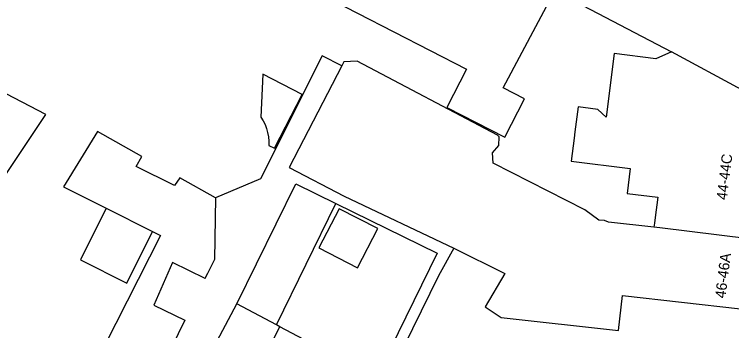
# Model space of a CAD drawing. Extents: x 160356 to 161355, y 381727 to 382845.
# Drawn here: x 160817.9 to 160886, y 382494.8 to 382524.8 of the extents above; entities that cross this region are included whole.
import ezdxf

# ---------------------------------------------------------------- set-up
doc = ezdxf.new("R2010")
doc.units = 0
for name, color, linetype in [('IMGEO_Pand', 7, 'Continuous'), ('IMGEO_Pand_nummerreeks', 7, 'Continuous'), ('IMGEO_Voetpad_open', 7, 'Continuous')]:
    doc.layers.add(name, color=color, linetype=linetype)

msp = doc.modelspace()

# ---------------------------------------------------------------- linework, layer by layer
at = {"layer": 'IMGEO_Pand'}
for points in [[(160824.152, 382533.852), (160837.584, 382526.234), (160838.848, 382528.417), (160837.315, 382530.354), (160831.623, 382533.804), (160833.49, 382536.883), (160835.203, 382535.845), (160836.729, 382538.894), (160838.441, 382538.049), (160837.071, 382535.496), (160839.161, 382530.801), (160840.132, 382530.297), (160860.857, 382519.63), (160858.986, 382515.995), (160864.495, 382513.16), (160866.366, 382516.795), (160864.324, 382517.846), (160869.25, 382527.097)], [(160812.331, 382502.558), (160820.876, 382515.321), (160798.417, 382527.033), (160799.163, 382528.464), (160793.416, 382531.651)], [(160870.515, 382526.431), (160880.329, 382521.263)], [(160880.329, 382521.263), (160878.832, 382520.606), (160874.881, 382521.106), (160874.119, 382515.078), (160873.323, 382515.802), (160872.618, 382515.891), (160871.438, 382516.04), (160871.139, 382513.68), (160871.062, 382513.069), (160870.786, 382510.885), (160876.395, 382510.176), (160876.098, 382507.826), (160879.006, 382507.459), (160878.761, 382505.521), (160878.695, 382505.002), (160878.645, 382504.609)], [(160889.248, 382516.338), (160887.01, 382517.677), (160880.329, 382521.263)], [(160848.991, 382519.946), (160844.007, 382510.297), (160849.223, 382507.566), (160859.631, 382502.608)], [(160878.645, 382504.609), (160874.318, 382505.075), (160873.965, 382505.255), (160873.402, 382505.285), (160872.096, 382506.277), (160863.365, 382510.705), (160863.301, 382511.662), (160863.907, 382512.364), (160863.939, 382513.212), (160863.779, 382513.371), (160850.449, 382520.387), (160849.186, 382520.324), (160848.991, 382519.946)], [(160841.313, 382515.071), (160841.522, 382514.726), (160841.7, 382514.362), (160841.843, 382513.984), (160841.951, 382513.595), (160842.022, 382513.197), (160842.057, 382512.794), (160842.055, 382512.39), (160842.591, 382512.113), (160845.23, 382517.222), (160841.505, 382519.147), (160841.313, 382515.071)], [(160837.001, 382507.39), (160833.605, 382509.304), (160833.101, 382508.558), (160829.451, 382510.383), (160830.003, 382511.334), (160825.776, 382513.717), (160822.543, 382508.456), (160826.615, 382506.409)], [(160839.03, 382497.328), (160844.617, 382508.729), (160848.441, 382506.855)], [(160837.001, 382507.39), (160836.886, 382501.545), (160836.243, 382500.225), (160836.06, 382499.851), (160836.009, 382499.745), (160832.921, 382501.249), (160831.125, 382497.218), (160834.076, 382495.78), (160827.844, 382482.992), (160825.738, 382478.624), (160823.529, 382474.138)], [(160826.615, 382506.409), (160824.157, 382501.519), (160828.563, 382499.304), (160831.021, 382504.193)], [(160826.615, 382506.409), (160831.021, 382504.193)], [(160842.79, 382495.323), (160848.441, 382506.855)], [(160846.827, 382502.645), (160850.499, 382500.756), (160852.413, 382504.477), (160848.741, 382506.366), (160846.827, 382502.645)], [(160831.021, 382504.193), (160831.756, 382503.824), (160824.368, 382489.208)], [(160887.658, 382503.498), (160879.203, 382504.549), (160878.645, 382504.609)], [(160859.631, 382502.608), (160858.18, 382500), (160854.89, 382493.275)], [(160859.631, 382502.608), (160864.483, 382500.207), (160862.624, 382497.041), (160864.148, 382496.031), (160875.287, 382494.796), (160875.655, 382498.111), (160886.875, 382496.851)], [(160837.157, 382493.816), (160839.03, 382497.328)], [(160842.79, 382495.323), (160839.03, 382497.328)], [(160843.093, 382495.161), (160842.79, 382495.323)], [(160839.805, 382488.578), (160843.657, 382486.524), (160847.118, 382493.014), (160843.093, 382495.161)], [(160840.928, 382490.826), (160843.093, 382495.161)]]:
    msp.add_lwpolyline(points, dxfattribs=at)
at = {"layer": 'IMGEO_Voetpad_open'}
for points in [[(160848.991, 382519.946), (160847.145, 382520.899), (160841.272, 382509.218), (160837.001, 382507.39)], [(160848.441, 382506.855), (160858.055, 382502.143), (160851.367, 382488.496), (160860.444, 382483.782), (160862.373, 382481.693), (160864.611, 382478.804)]]:
    msp.add_lwpolyline(points, dxfattribs=at)

# ---------------------------------------------------------------- texts
at = {"layer": 'IMGEO_Pand_nummerreeks'}
for s, rotation, p in [('44-44C', 82.9471, (160885.573, 382507.159)), ('46-46A', 82.86689, (160885.434, 382497.81))]:
    msp.add_text(s, height=1, rotation=rotation, dxfattribs=at).set_placement(p)

doc.saveas('drawing.dxf')
